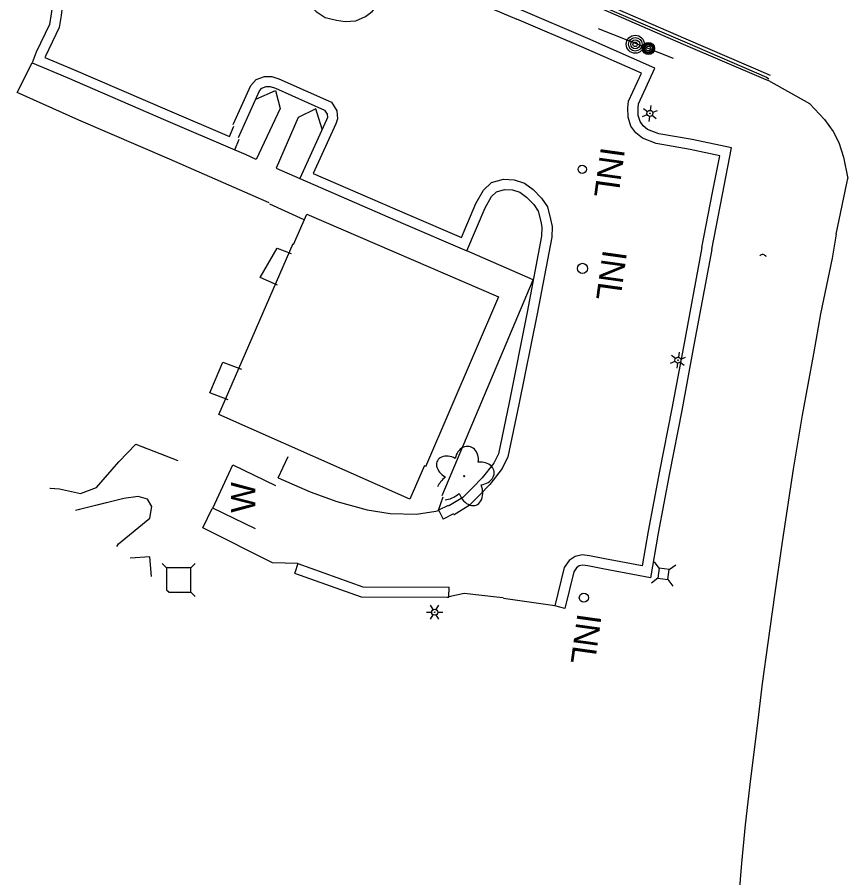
# Model space of a CAD drawing. Extents: x 588843 to 2552415, y 180129 to 269402.
# Drawn here: x 593027.1 to 593232.6, y 185185.1 to 185398.1 of the extents above; entities that cross this region are included whole.
import ezdxf

# ---------------------------------------------------------------- set-up
doc = ezdxf.new("R2010")
doc.units = 0
for name, color, linetype in [('Default', 7, 'Continuous'), ('E_BLD', 7, 'Continuous'), ('E_DRN', 7, 'Continuous'), ('E_DRN_Text', 7, 'Continuous'), ('E_DWY', 7, 'Continuous'), ('E_LAND_Vegetation', 7, 'Continuous'), ('E_LTG', 7, 'Continuous'), ('E_MISCPROP', 7, 'Continuous'), ('E_PATH_Sidewalk', 7, 'Continuous'), ('E_RDWY', 7, 'Continuous'), ('E_RDWY_C_and_G', 7, 'Continuous'), ('E_SGN', 7, 'Continuous'), ('E_UTL_AG_Bold', 7, 'Continuous'), ('E_UTL_MH', 7, 'Continuous'), ('Level 15', 7, 'Continuous'), ('Level 17', 7, 'Continuous'), ('Level 19', 7, 'Continuous'), ('Level 21', 7, 'Continuous')]:
    doc.layers.add(name, color=color, linetype=linetype)

# ---------------------------------------------------------------- blocks, each defined once
blk = doc.blocks.new('INLT_19')
at = {"layer": 'E_DRN_Text'}
blk.add_text('INL', height=12, dxfattribs=at).set_placement((-11.03, -6))
blk = doc.blocks.new('LPOL')
at = {"layer": 'Default'}
for p, q in [((-4, 0), (-1.5, 0)), ((-0.75, 1.3), (-2, 3.46)), ((0.75, 1.3), (2, 3.46)), ((1.5, 0), (4, 0)), ((-2, -3.46), (-0.75, -1.3)), ((2, -3.46), (0.75, -1.3))]:
    blk.add_line(p, q, dxfattribs=at)
for radius in [1.5, 1.5, 1.5, 0.125]:
    blk.add_circle((0, 0), radius, dxfattribs=at)
blk = doc.blocks.new('CULV2')
at = {"layer": 'E_DRN'}
blk.add_arc((19.7, 14.8), 24.6, 216.8699, 323.1301, dxfattribs=at)
blk = doc.blocks.new('PED')
at = {"layer": 'Default'}
for p, q in [((-2.5, 2.5), (-5.33, 5.33)), ((2.5, 2.5), (5.33, 5.33)), ((-2.5, -2.5), (-5.33, -5.33)), ((2.5, -2.5), (5.33, -5.33))]:
    blk.add_line(p, q, dxfattribs=at)
blk.add_lwpolyline([(-2.5, -2.5), (2.5, -2.5), (2.5, 2.5), (-2.5, 2.5)], close=True, dxfattribs=at)
blk = doc.blocks.new('MHO')
at = {"layer": 'Default'}
for centre, radius in [((0.08, -0.12), 3), ((0.08, -0.12), 2.43), ((0.07, -0.15), 1.94), ((0.02, -0.16), 1.21)]:
    blk.add_circle(centre, radius, dxfattribs=at)
blk = doc.blocks.new('POLE')
at = {"layer": 'Default'}
for radius in [4.46, 3.35, 2.23, 1.12]:
    blk.add_circle((0, 0), radius, dxfattribs=at)

msp = doc.modelspace()

# ---------------------------------------------------------------- linework, layer by layer
at = {"layer": 'E_BLD'}
for points in [[(593095.49, 185341.88), (593098.72, 185349.36), (593146.21, 185328.9), (593128.09, 185286.85)], [(593127.9, 185287.18), (593124.28, 185278.83), (593077.01, 185299.76), (593095.36, 185342.09)]]:
    msp.add_lwpolyline(points, dxfattribs=at)
at = {"layer": 'E_DRN'}
for centre, radius in [((593166.92, 185360.47), 1.04), ((593166.98, 185335.96), 1.26), ((593167.31, 185254.46), 1.13)]:
    msp.add_circle(centre, radius, dxfattribs=at)
at = {"layer": 'E_DWY'}
for points in [[(593121.84, 185424.79), (593118.51, 185425.14), (593115.75, 185424.92), (593112.36, 185424.02), (593109.2, 185422.54), (593106.35, 185420.72), (593103.94, 185418.8), (593101.27, 185415.74), (593099.58, 185413.32), (593097.81, 185408.85), (593097.12, 185406.02), (593097.38, 185403.59), (593098.77, 185401.6), (593101.1, 185399.54), (593103.31, 185398.04), (593106.11, 185397.35), (593108.25, 185397.08), (593110.92, 185397.23), (593113.25, 185398.32), (593114.91, 185399.49), (593115.99, 185400.77), (593120.33, 185410.63), (593135.91, 185404.02), (593150.72, 185397.64)], [(593198.99, 185340.64), (593201.57, 185354.25), (593203.86, 185365.78), (593194.1, 185367.81), (593185.89, 185369.29), (593183.05, 185370.36), (593182, 185371.22), (593181.21, 185372.3), (593180.74, 185373.81), (593180.72, 185375.61), (593180.82, 185376.67), (593184.88, 185385.51), (593168.3, 185392.86), (593151.7, 185399.94)], [(593196.53, 185341.11), (593199.12, 185354.73), (593200.93, 185363.84), (593193.62, 185365.35), (593185.22, 185366.87), (593181.78, 185368.17), (593180.17, 185369.49), (593178.95, 185371.16), (593178.24, 185373.41), (593178.22, 185375.71), (593178.37, 185377.32), (593181.55, 185384.25), (593167.3, 185390.57), (593150.72, 185397.64)], [(593080.55, 185371.54), (593084.94, 185381.24), (593086.19, 185382.67), (593088.3, 185383.45), (593090.1, 185383.43), (593091.86, 185382.89), (593104.89, 185377.1), (593106.22, 185374.92), (593106.38, 185372.96), (593105.94, 185371.76), (593100.34, 185359.44), (593123.59, 185349.37), (593137.01, 185343.58), (593140.6, 185352.04), (593142.46, 185355.35), (593144.48, 185357.18), (593147.43, 185358), (593150.07, 185357.85), (593152.58, 185357.05), (593154.8, 185355.45), (593156.83, 185353.33), (593158.34, 185351.17), (593159.07, 185348.11), (593159.43, 185346.33), (593159.36, 185343.64), (593155.72, 185324.67), (593151.24, 185302.27), (593148.53, 185289.28), (593147.11, 185286.41), (593144.01, 185282.51), (593141.55, 185279.91), (593138.96, 185277.26), (593135.21, 185275), (593135.13, 185274.97)], [(593081.85, 185368.36), (593087.06, 185379.87), (593087.65, 185380.54), (593088.73, 185380.95), (593089.71, 185380.93), (593090.99, 185380.54), (593103.16, 185375.13), (593103.78, 185374.12), (593103.84, 185373.31), (593103.62, 185372.71), (593097.02, 185358.16), (593122.6, 185347.07), (593138.32, 185340.29), (593142.85, 185350.93), (593144.44, 185353.77), (593145.72, 185354.93), (593147.7, 185355.48), (593149.61, 185355.37), (593151.44, 185354.79), (593153.15, 185353.55), (593154.89, 185351.74), (593156.02, 185350.12), (593156.63, 185347.57), (593156.92, 185346.12), (593156.86, 185343.91), (593153.26, 185325.15), (593148.79, 185302.77), (593146.15, 185290.1), (593144.99, 185287.76), (593142.12, 185284.15), (593139.74, 185281.64), (593137.4, 185279.24), (593134.08, 185277.24), (593133.84, 185277.14)], [(593196.53, 185341.11), (593191.92, 185316.58), (593189.09, 185301.27), (593186.06, 185285.78), (593183.25, 185270.91), (593181.77, 185262.32), (593172.47, 185264.08), (593168.69, 185264.8), (593166.9, 185265.09), (593165.18, 185264.67), (593163.67, 185263.7), (593162.47, 185261.89), (593160.15, 185252.41)], [(593198.99, 185340.64), (593194.38, 185316.12), (593191.54, 185300.8), (593188.52, 185285.31), (593185.71, 185270.46), (593183.81, 185259.39), (593172, 185261.62), (593168.26, 185262.34), (593167, 185262.54), (593166.18, 185262.34), (593165.47, 185261.88), (593164.79, 185260.87), (593162.58, 185251.82)], [(593135.21, 185275), (593135.13, 185274.97)], [(593162.58, 185251.82), (593160.15, 185252.41), (593147.41, 185254.25)]]:
    msp.add_lwpolyline(points, dxfattribs=at)
at = {"layer": 'E_LAND_Vegetation'}
msp.add_circle((593137.68, 185284.53), 0.128, dxfattribs=at)
for centre, major_axis, ratio, start_param, end_param in [((593138.33, 185288.46), (-0.56, -3.41), 0.832022, 1.570796, 4.712389), ((593134.26, 185286.64), (3.19, -1.72), 0.716896, 1.570796, 4.712389), ((593141.53, 185285.19), (-3.58, -0.46), 0.782863, 1.570796, 4.712389), ((593134.75, 185282.31), (3.66, 3.03), 0.560249, 1.570796, 2.290398), ((593139.16, 185281.33), (-1.52, 3.94), 0.691916, 1.570796, 4.712389), ((593134.75, 185282.31), (3.66, 3.03), 0.560249, 3.815979, 4.712389)]:
    msp.add_ellipse(centre, major_axis=major_axis, ratio=ratio, start_param=start_param, end_param=end_param, dxfattribs=at)
at = {"layer": 'E_LTG'}
for p, q in [((593130.03, 185251.52), (593129.4, 185252.6)), ((593130.78, 185251.52), (593131.4, 185252.6)), ((593128.4, 185250.87), (593129.65, 185250.87)), ((593129.4, 185249.14), (593130.03, 185250.22)), ((593131.4, 185249.14), (593130.78, 185250.22)), ((593131.15, 185250.87), (593132.4, 185250.87))]:
    msp.add_line(p, q, dxfattribs=at)
for radius in [0.75, 0.75, 0.75, 0.0625]:
    msp.add_circle((593130.4, 185250.87), radius, dxfattribs=at)
at = {"layer": 'E_PATH_Sidewalk'}
for points in [[(593086.15, 185377.85), (593091.01, 185379.95), (593092.17, 185375.5), (593086.25, 185362.9), (593083.58, 185364.12)], [(593102.57, 185370.39), (593100.98, 185375.41), (593096.65, 185373.33), (593091.21, 185360.77), (593097.02, 185358.16)], [(593098.12, 185347.99), (593089.57, 185351.86)], [(593132.28, 185279.78), (593154.79, 185333.09), (593138.32, 185340.29)]]:
    msp.add_lwpolyline(points, dxfattribs=at)
at = {"layer": 'E_RDWY'}
for points in [[(593213.03, 185382.42), (593223.1, 185376.74), (593226.86, 185372.78), (593229.03, 185369.82), (593230.4, 185367.11), (593231.53, 185363.51), (593232.61, 185358.23)], [(593229.75, 185344.39), (593232.36, 185357.06), (593232.61, 185358.23)], [(593229.75, 185344.39), (593228.74, 185338.48), (593225.9, 185324.71), (593224.11, 185314.81), (593221.31, 185299.66), (593219.1, 185286.27), (593216.35, 185268.31), (593214.44, 185255.05), (593212.81, 185243.32), (593211.42, 185233.23), (593210.18, 185222.75), (593208.56, 185209.67), (593207.25, 185198.27), (593206.31, 185188.73), (593205.22, 185175.67), (593204.19, 185161.83), (593203.37, 185148.48), (593202.75, 185137.01), (593202.17, 185127.15), (593201.68, 185113.66), (593201.21, 185098.92), (593200.87, 185085.43), (593200.59, 185062.46), (593200.61, 185054.59)]]:
    msp.add_lwpolyline(points, dxfattribs=at)
at = {"layer": 'E_RDWY_C_and_G'}
for points in [[(593168.17, 185401.78), (593191.88, 185391.42), (593212.35, 185382.7), (593213.03, 185382.42)], [(593168.46, 185402.26), (593192.28, 185392.02), (593212.46, 185383.24), (593213.1, 185382.87)], [(593168.75, 185403.12), (593192.57, 185392.77), (593213.37, 185383.8)]]:
    msp.add_lwpolyline(points, dxfattribs=at)
at = {"layer": 'E_SGN'}
msp.add_lwpolyline([(593189.51, 185387.9), (593170.9, 185395.23)], dxfattribs=at)
at = {"layer": 'Level 15'}
msp.add_lwpolyline([(593086.03, 185271.52), (593075.54, 185276.65), (593080.43, 185287.37), (593091.04, 185282.22)], dxfattribs=at)
at = {"layer": 'Level 17'}
for points in [[(593029.12, 185409.4), (593028.37, 185407.13), (593028.34, 185407.03), (593031.42, 185406.01), (593033.92, 185404.48), (593035.41, 185402.65), (593035.71, 185400.65), (593035.53, 185398.92), (593035.07, 185396.31), (593031.75, 185389.44), (593030.8, 185386.79)], [(593029.12, 185409.4), (593032.48, 185408.29), (593035.58, 185406.39), (593037.79, 185403.71), (593038.23, 185400.71), (593038.01, 185398.57), (593037.47, 185395.54), (593034.06, 185388.48), (593033.95, 185388.18), (593040.42, 185385.46), (593064.74, 185374.93), (593079.59, 185368.56), (593080.71, 185371.16)], [(593089.44, 185352.14), (593064.81, 185363), (593042.31, 185372.66), (593027.1, 185379.48), (593030.8, 185386.79)], [(593030.8, 185386.79), (593039.44, 185383.16), (593063.75, 185372.63), (593080.91, 185365.27)], [(593080.91, 185365.27), (593082.04, 185367.91)], [(593080.91, 185365.27), (593083.53, 185364.26)], [(593091.5, 185331.81), (593087.25, 185333.71), (593091.39, 185340.98), (593094.88, 185339.66)], [(593079.3, 185303.46), (593074.73, 185305.16), (593077.97, 185312.74), (593082.56, 185311.03)], [(593091.7, 185284.13), (593094.12, 185289.39)], [(593091.7, 185284.13), (593099.56, 185280.64), (593106.2, 185278.24), (593113.66, 185276.21), (593119.39, 185275.3), (593125.92, 185275.14), (593130.7, 185275.86), (593131.32, 185276)], [(593131.35, 185276.11), (593132.47, 185279.46)], [(593096.56, 185262.88), (593090.25, 185263.05), (593072.99, 185271.73), (593075.32, 185276.55)], [(593131.32, 185276), (593131.4, 185276.02)], [(593133.74, 185277.31), (593131.35, 185276.11)], [(593131.35, 185276.11), (593131.4, 185276.02)], [(593131.4, 185276.02), (593132.48, 185273.87)], [(593135.09, 185275.19), (593132.48, 185273.87)], [(593060.29, 185259.69), (593059.94, 185264.6), (593055.05, 185264.25)], [(593055.05, 185264.25), (593055.05, 185264.25)], [(593096.56, 185262.88), (593095.76, 185260.62), (593095.72, 185260.52), (593112.2, 185254.67), (593133.46, 185254.59)], [(593096.56, 185262.88), (593112.64, 185257.16), (593133.94, 185257.09)], [(593133.93, 185254.69), (593133.94, 185257.09)], [(593133.46, 185254.59), (593133.93, 185254.59), (593133.93, 185254.69)], [(593147.31, 185254.41), (593145.65, 185254.61), (593137.73, 185255.48), (593133.93, 185254.69)]]:
    msp.add_lwpolyline(points, dxfattribs=at)
at = {"layer": 'Level 19'}
for points in [[(593035.21, 185281.55), (593037.55, 185281.4), (593042.75, 185280.27), (593046.68, 185281.72), (593052.26, 185288.1), (593056.43, 185292.43), (593066.82, 185288.42)], [(593035.21, 185281.55), (593037.55, 185281.4), (593042.75, 185280.27), (593046.68, 185281.72), (593052.26, 185288.1), (593056.43, 185292.43), (593058.91, 185291.48)], [(593062.64, 185290.03), (593064.5, 185289.31)], [(593035.2, 185281.55), (593035.21, 185281.55)], [(593051.78, 185267.09), (593052.15, 185267.75), (593059.95, 185274.18), (593060.38, 185277.01), (593059.37, 185278.84), (593056.99, 185279.48), (593053.51, 185278.99), (593045.5, 185277.02), (593041.5, 185276.04)], [(593051.78, 185267.09), (593052.15, 185267.75), (593059.95, 185274.18), (593060.38, 185277.01), (593059.37, 185278.84), (593056.99, 185279.48), (593053.51, 185278.99), (593046.51, 185277.27)], [(593042.62, 185276.32), (593041.5, 185276.04)]]:
    msp.add_lwpolyline(points, dxfattribs=at)
at = {"layer": 'Level 21'}
for p, q in [((593064.04, 185261.84), (593062.98, 185262.9)), ((593070.04, 185261.84), (593071.1, 185262.9)), ((593064.04, 185261.84), (593064.04, 185256.42)), ((593070.04, 185261.84), (593064.04, 185261.84)), ((593070.04, 185255.84), (593070.04, 185261.84)), ((593064.04, 185256.42), (593064.71, 185255.84)), ((593064.71, 185255.84), (593070.04, 185255.84)), ((593071.1, 185254.78), (593070.04, 185255.84))]:
    msp.add_line(p, q, dxfattribs=at)

# ---------------------------------------------------------------- block references
at = {"layer": 'E_DRN', "xscale": 0.04148756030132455, "yscale": 0.041487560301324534, "rotation": 171.25151395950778}
msp.add_blockref('CULV2', (593212.43, 185338.83), dxfattribs=at)
at = {"layer": 'E_DRN_Text', "xscale": 0.49999999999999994, "yscale": 0.49999999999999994, "rotation": -97.93561972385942}
for p in [(593173.76, 185360.31), (593174.26, 185334.86), (593167.96, 185244.87)]:
    msp.add_blockref('INLT_19', p, dxfattribs=at)
at = {"layer": 'E_LTG', "xscale": 0.49999999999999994, "yscale": 0.49999999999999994, "rotation": -97.93561972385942}
for p in [(593183.64, 185374.3), (593190.58, 185313.24)]:
    msp.add_blockref('LPOL', p, dxfattribs=at)
at = {"layer": 'E_MISCPROP', "xscale": 0.4999999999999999, "yscale": 0.4999999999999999, "rotation": -23.35379701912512}
msp.add_blockref('POLE', (593180.02, 185391.41), dxfattribs=at)
at = {"layer": 'E_UTL_AG_Bold', "xscale": 0.49999999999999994, "yscale": 0.49999999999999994, "rotation": -97.93561972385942}
msp.add_blockref('PED', (593187.04, 185260.35), dxfattribs=at)
at = {"layer": 'E_UTL_MH', "xscale": 0.4999999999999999, "yscale": 0.4999999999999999, "rotation": -23.35379701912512}
msp.add_blockref('MHO', (593183.29, 185390.45), dxfattribs=at)

# ---------------------------------------------------------------- texts
at = {"layer": 'Level 15'}
msp.add_text('W', height=6, rotation=90, dxfattribs=at).set_placement((593085.98, 185275.48))

doc.saveas('drawing.dxf')
